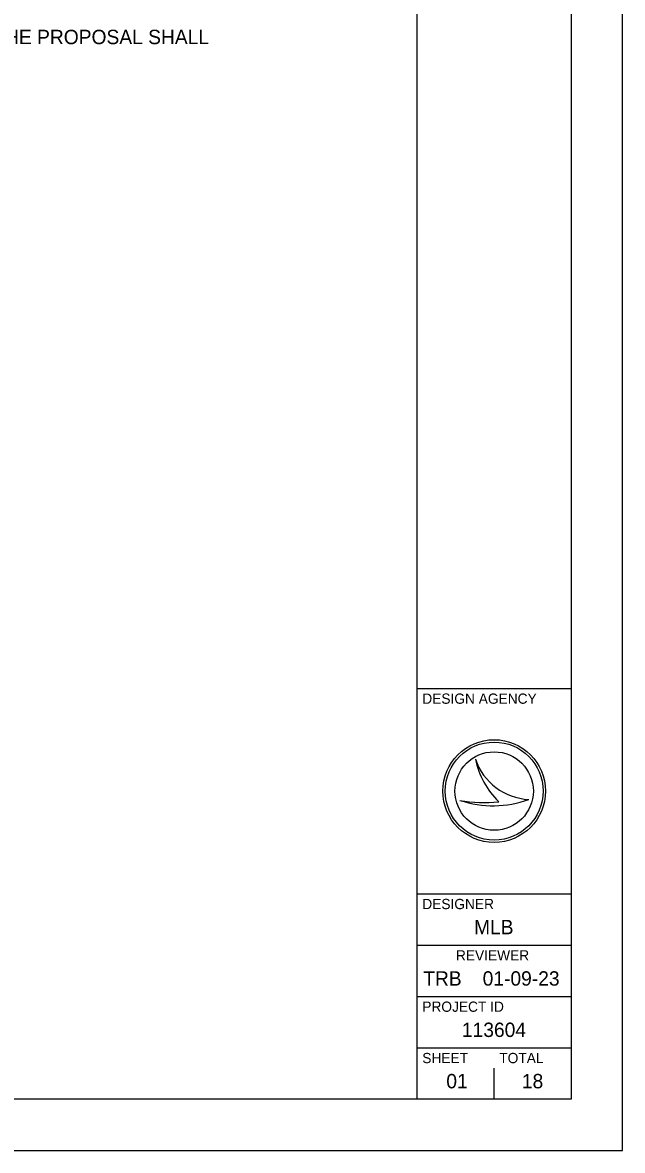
# Model space of a CAD drawing. Extents: x 43.1 to 77.1, y 2.7 to 24.7.
# Drawn here: x 71.29 to 77.13, y 2.66 to 13.64 of the extents above; entities that cross this region are included whole.
import ezdxf

# ---------------------------------------------------------------- set-up
doc = ezdxf.new("R2010")
doc.units = 0
for name, color, linetype in [('SH_Border', 7, 'Continuous'), ('SH_Cut_Line', 7, 'Continuous'), ('SH_Data', 7, 'Continuous'), ('SH_Text', 7, 'Continuous')]:
    doc.layers.add(name, color=color, linetype=linetype)

msp = doc.modelspace()

# ---------------------------------------------------------------- linework, layer by layer
at = {"layer": 'SH_Border'}
for p, q in [((75.131, 3.158), (75.131, 24.158)), ((75.131, 7.158), (76.631, 7.158)), ((75.131, 5.158), (76.631, 5.158)), ((75.131, 4.658), (76.631, 4.658)), ((75.131, 4.158), (76.631, 4.158)), ((75.131, 3.658), (76.631, 3.658))]:
    msp.add_line(p, q, dxfattribs=at)
msp.add_lwpolyline([(44.631, 24.158), (76.631, 24.158), (76.631, 3.158), (44.631, 3.158)], close=True, dxfattribs=at)
at = {"layer": 'SH_Cut_Line'}
msp.add_lwpolyline([(43.131, 2.658), (77.131, 2.658), (77.131, 24.658), (43.131, 24.658)], close=True, dxfattribs=at)
at = {"layer": 'SH_Data'}
for p, q in [((75.698, 6.468), (75.698, 6.468)), ((75.881, 6.158), (75.881, 6.158)), ((75.548, 6.068), (75.548, 6.068)), ((76.218, 6.077), (76.218, 6.077)), ((75.881, 3.158), (75.881, 3.458)), ((75.506, 3.333), (75.506, 3.333))]:
    msp.add_line(p, q, dxfattribs=at)
for radius in [0.5, 0.477, 0.477, 0.382]:
    msp.add_circle((75.881, 6.158), radius, dxfattribs=at)
for centre, radius, start, end in [((76.247, 6.656), 0.58, 198.9257, 198.9319), ((76.478, 6.628), 0.796, 191.6379, 191.6421), ((76.247, 6.656), 0.58, 198.9319, 267.1657), ((76.478, 6.628), 0.796, 191.6421, 226.0947), ((75.87, 7.028), 1.013, 251.4576, 290.0832), ((75.779, 7.312), 1.266, 259.4964, 259.4995), ((75.87, 7.028), 1.013, 251.4527, 251.4576), ((75.779, 7.312), 1.266, 259.4995, 276.6672)]:
    msp.add_arc(centre, radius, start, end, dxfattribs=at)

# ---------------------------------------------------------------- texts
for s, height, p in [('DESIGN AGENCY', 0.1, (75.181, 7.008)), ('DESIGNER', 0.1, (75.181, 5.008)), ('MLB', 0.14, (75.685, 4.763)), ('REVIEWER', 0.1, (75.509, 4.508)), ('TRB', 0.14, (75.19, 4.263)), ('01-09-23', 0.14, (75.769, 4.263)), ('PROJECT ID', 0.1, (75.181, 4.008)), ('113604', 0.14, (75.567, 3.763)), ('SHEET', 0.1, (75.181, 3.508)), ('TOTAL', 0.1, (75.931, 3.508)), ('01', 0.14, (75.415, 3.263)), ('18', 0.14, (76.151, 3.263))]:
    msp.add_text(s, height=height, dxfattribs=at).set_placement(p)
at = {"layer": 'SH_Text'}
msp.add_text('PLANS AND CHANGES LISTED IN THE PROPOSAL SHALL', height=0.14, dxfattribs=at).set_placement((67.964, 13.432))

doc.saveas('drawing.dxf')
